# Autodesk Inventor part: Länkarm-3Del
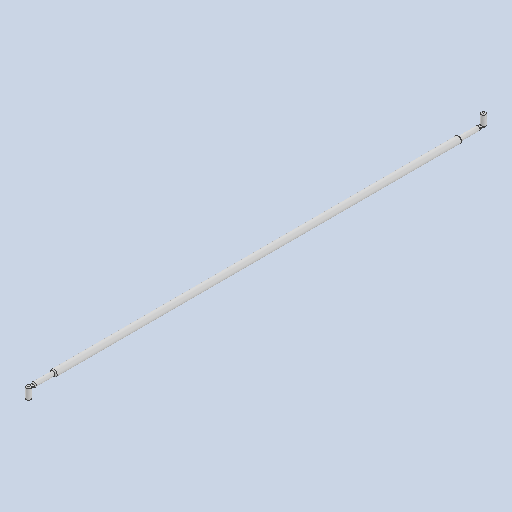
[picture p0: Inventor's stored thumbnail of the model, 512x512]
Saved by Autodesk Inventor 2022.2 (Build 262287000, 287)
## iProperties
Created: 2022-03
Part Number: Länkarm-3Del
Material: Generic
Document SubType Name: Modeling
Designer: cl
Density: 1 g/cm^3
Appearance: Default
Author: cl
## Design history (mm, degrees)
sketch "Sketch1"
  geometry: L1 (0, 0)-(0, -2016.11); L2 (0, 0)-(-10, 0); L3 (-10, 0)-(-10, -90); L4 (-10, -90)-(-15, -90); L5 (-15, -90)-(-15, -1926.11); L6 (0, -2016.11)-(-10, -2016.11); L7 (-10, -2016.11)-(-10, -1926.11); L8 (-10, -1926.11)-(-15, -1926.11); 1 further point
  constraints: 16 end point, 5 perpendicular, 2 horizontal, 1 midpoint, 1 vertical
  dimensions: "d0" = 2016.11 distance of L1.start L1.end (computed from BladBredd); "d1" = 20 diameter of L3 L1; "d2" = 5 distance between parallel lines of L3 L5; "d3" = 90 distance of L2.end L3.end; "d4" = 20 diameter of L7 L1; "d5" = 90 vertical distance of point (-5, -2016.11) L5.end
revolve "Revolution1" sketch "Sketch1" stored, may be unused: angle "d6" = 90 deg
fillet "Fillet1" dims "d7" = 5
workplane "Work Plane1"
sketch "Sketch2"
  geometry: L1 (10, 0)-(-10, 0) reference; L2 (7.5, 0)-(-7.5, 0); L3 (-7.5, 0)-(-7.5, 20); L4 (-7.5, 20)-(7.5, 20); L5 (7.5, 20)-(7.5, 0); L6 (10, -90)-(10, 0) reference; L7 (10, -2016.11)-(-10, -2016.11) reference; L8 (7.5, -2016.11)-(-7.5, -2016.11); L9 (-7.5, -2016.11)-(-7.5, -2036.11); L10 (-7.5, -2036.11)-(7.5, -2036.11); L11 (7.5, -2036.11)-(7.5, -2016.11); 3 further points
  constraints: 16 end point, 4 parallel, 2 horizontal, 2 perpendicular, 2 point on line, 1 collinear
  dimensions: "d9" = 2.5 distance between parallel lines of L5 L6; "d10" = 15 distance of L3.end L4.end; "d11" = 20 distance of L2.end L3.end; "d12" = 20 distance of L8.end L9.end; "d13" = 15 distance of L9.end L10.end
extrude "Extrusion1" join sketch "Sketch2" distance "d14" = 4; taper "d15" = 0 deg
sketch "Sketch3"
  geometry: L1 (7.5, 20)-(-7.5, 20) reference; L2 (-7.5, -2036.11)-(7.5, -2036.11) reference; C1 r 10 at (0, 20); C2 r 10 at (0, -2036.11); 1 further point
  constraints: 2 centre point, 2 midpoint
  dimensions: "d16" = 20 diameter of C1; "d17" = 20 diameter of C2
extrude "Extrusion2" join sketch "Sketch3" distance "d18" = 8; taper "d20" = 0 deg; dims "d19" = 48, "d21" = 0
extrude "Extrusion3" join sketch "Sketch3" distance "d22" = 50; taper "d24" = 0 deg; dims "d23" = 6, "d25" = 0
fillet "Fillet2" dims "d26" = 5
body "Solid1"
other parameters: "BladBredd" = 1333.33333, "Fönsterhöjd" = 862, "Blad2" = 1358.33333, "Blad3" = 0, "Blad4" = 0, "Blad5" = 0, "Blad6" = 2025, "MGJ12Djup" = 0, "MGJ12Bredd" = 0, "MGJ2Djup" = 0, "MGJ2Bredd" = 5012.5, "MGJ56Djup" = 48, "MGJ23Djup" = 48, "MGJ45Djup" = 48, "GarageRegel5" = 0, "GarageRegel6" = 0, "StyrskenaV" = 2766.66667, "Styrrulle2Djup" = 48, "FönsterhöjdStyrning" = 862, "FönsterKarm" = 54, "AndraGlasraden" = 0, "BrösthöjdStyrning2" = 0.0001, "InfälldGångDörr" = 0, "Infälldstyr" = 1012.5, "EnDelGångDörr" = 0, "VinkelJärnStyrSkena" = 2666.66667, "d8" = -2
